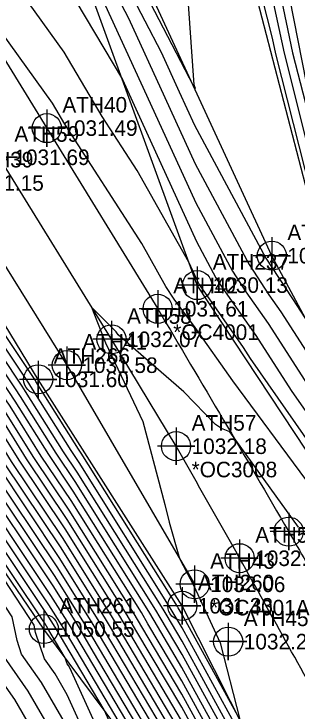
# Model space of a CAD drawing. Extents: x 1213164 to 1213550, y 766120 to 766870.
# Drawn here: x 1213382.8 to 1213428.3, y 766180 to 766292.1 of the extents above; entities that cross this region are included whole.
import ezdxf

# ---------------------------------------------------------------- set-up
doc = ezdxf.new("R2010")
doc.units = 0
for name, color, linetype in [('Default', 7, 'Continuous'), ('Exist DTM Breakline', 7, 'Continuous'), ('Exist DTM Breakline Cogo Elevation', 7, 'Continuous'), ('Exist DTM Breakline Cogo Number', 7, 'Continuous'), ('Exist DTM Breakline Cogo Point CELL', 7, 'Continuous'), ('Exist DTM Crownline', 7, 'Continuous'), ('Exist DTM Crownline Cogo Comment', 7, 'Continuous'), ('Exist DTM Crownline Cogo Elevation', 7, 'Continuous'), ('Exist DTM Crownline Cogo Number', 7, 'Continuous'), ('Exist DTM Crownline Cogo Point CELL', 7, 'Continuous'), ('Exist DTM Regular Point Cogo Comment', 7, 'Continuous'), ('Exist DTM Regular Point Cogo Elevation', 7, 'Continuous'), ('Exist DTM Regular Point Cogo Number', 7, 'Continuous'), ('Exist Hydro Stream or Body of Water', 7, 'Continuous'), ('Exist Roads EOP', 7, 'Continuous'), ('Exist Roads EOP Cogo Point CELL', 7, 'Continuous')]:
    doc.layers.add(name, color=color, linetype=linetype)

msp = doc.modelspace()

# ---------------------------------------------------------------- linework, layer by layer
at = {"layer": 'Default'}
for points in [[(1213425.78, 766168.77), (1213421.23, 766170.35), (1213409.8, 766191.25), (1213407.24, 766195.57), (1213406.74, 766196.41), (1213392.93, 766218.45), (1213390.76, 766221.69), (1213384.66, 766231.42), (1213384.09, 766232.28), (1213370.2, 766253.11), (1213367.37, 766257.44), (1213361.68, 766265.98), (1213357.81, 766271.9), (1213346.18, 766291.12), (1213344.45, 766293.74), (1213344.38, 766293.85), (1213332.56, 766311.61), (1213326.86, 766318.42), (1213322.03, 766325.64), (1213318.4, 766329.89), (1213314.05, 766335.72), (1213304.75, 766347.47), (1213303.88, 766348.56), (1213294.86, 766355.65)], [(1213427.02, 766169.17), (1213422.12, 766170.87), (1213409.81, 766193.38), (1213408.21, 766196.08), (1213407.9, 766196.6), (1213393.25, 766219.97), (1213391.95, 766221.91), (1213385.49, 766232.22), (1213385.15, 766232.72), (1213370.45, 766254.79), (1213368.43, 766257.88), (1213362.35, 766267), (1213359.46, 766271.43), (1213346.86, 766292.25), (1213345.54, 766294.24), (1213345.47, 766294.36), (1213332.57, 766313.73), (1213328.14, 766319.03), (1213322.73, 766327.12), (1213319.88, 766330.46), (1213316.46, 766335.04), (1213305.27, 766349.17), (1213304.23, 766350.49), (1213296.83, 766356.3)], [(1213424.54, 766168.36), (1213420.34, 766169.83), (1213409.79, 766189.12), (1213406.27, 766195.06), (1213405.59, 766196.21), (1213392.6, 766216.92), (1213389.56, 766221.46), (1213383.82, 766230.62), (1213383.02, 766231.83), (1213369.96, 766251.43), (1213366.3, 766257.01), (1213361.02, 766264.95), (1213356.16, 766272.38), (1213345.5, 766290), (1213343.35, 766293.24), (1213343.29, 766293.34), (1213332.54, 766309.48), (1213325.58, 766317.82), (1213321.33, 766324.16), (1213316.92, 766329.32), (1213311.63, 766336.4), (1213304.22, 766345.77), (1213303.53, 766346.64), (1213292.88, 766355.01)], [(1213422.06, 766167.56), (1213418.56, 766168.78), (1213409.76, 766184.86), (1213404.32, 766194.05), (1213403.27, 766195.83), (1213391.96, 766213.87), (1213387.17, 766221.02), (1213382.16, 766229.02), (1213380.88, 766230.94), (1213369.46, 766248.07), (1213364.18, 766256.14), (1213359.68, 766262.9), (1213352.86, 766273.33), (1213344.14, 766287.74), (1213341.16, 766292.24), (1213341.11, 766292.32), (1213332.51, 766305.24), (1213323.02, 766316.6), (1213319.94, 766321.2), (1213313.97, 766328.18), (1213306.81, 766337.76), (1213303.18, 766342.36), (1213302.84, 766342.79), (1213288.93, 766353.71)], [(1213423.3, 766167.96), (1213419.45, 766169.3), (1213409.77, 766186.99), (1213405.3, 766194.56), (1213404.43, 766196.02), (1213392.28, 766215.39), (1213388.37, 766221.24), (1213382.99, 766229.82), (1213381.95, 766231.39), (1213369.71, 766249.75), (1213365.24, 766256.58), (1213360.35, 766263.93), (1213354.51, 766272.85), (1213344.82, 766288.87), (1213342.26, 766292.74), (1213342.2, 766292.83), (1213332.53, 766307.36), (1213324.3, 766317.21), (1213320.64, 766322.68), (1213315.45, 766328.75), (1213309.22, 766337.08), (1213303.7, 766344.06), (1213303.19, 766344.71), (1213290.91, 766354.36)], [(1213419.58, 766166.76), (1213416.78, 766167.74), (1213409.74, 766180.61), (1213402.38, 766193.03), (1213400.96, 766195.44), (1213391.31, 766210.82), (1213384.78, 766220.58), (1213380.5, 766227.42), (1213378.74, 766230.05), (1213368.97, 766244.72), (1213362.06, 766255.27), (1213358.34, 766260.85), (1213349.57, 766274.28), (1213342.78, 766285.49), (1213338.97, 766291.24), (1213338.94, 766291.3), (1213332.48, 766300.99), (1213320.46, 766315.38), (1213318.55, 766318.23), (1213311.02, 766327.04), (1213302.39, 766338.6), (1213302.07, 766338.95), (1213301.81, 766339.2), (1213284.98, 766352.42)], [(1213420.82, 766167.16), (1213417.67, 766168.26), (1213409.75, 766182.74), (1213403.35, 766193.54), (1213402.12, 766195.63), (1213391.64, 766212.34), (1213385.98, 766220.8), (1213381.33, 766228.22), (1213379.81, 766230.49), (1213369.21, 766246.39), (1213363.12, 766255.71), (1213359.01, 766261.88), (1213351.22, 766273.8), (1213343.46, 766286.61), (1213340.07, 766291.74), (1213340.02, 766291.81), (1213332.5, 766303.12), (1213321.74, 766315.99), (1213319.25, 766319.71), (1213312.5, 766327.61), (1213304.4, 766338.44), (1213302.65, 766340.66), (1213302.49, 766340.86), (1213286.96, 766353.07)], [(1213410.14, 766303.65), (1213406.71, 766314.59), (1213392.41, 766329.73), (1213391.36, 766332.12), (1213385.67, 766331.97), (1213377.74, 766344.17), (1213376.85, 766345.21), (1213377.45, 766344.02), (1213377.59, 766343.78), (1213386.05, 766328.27), (1213386.98, 766326.67), (1213400.49, 766302.03), (1213411.64, 766280.51), (1213411.65, 766280.47), (1213411.66, 766280.44), (1213411.77, 766280.25), (1213411.98, 766280.11), (1213411.81, 766280.54), (1213411.74, 766280.72), (1213410.14, 766303.65)], [(1213418.34, 766166.36), (1213415.89, 766167.21), (1213409.72, 766178.48), (1213401.41, 766192.53), (1213399.8, 766195.24), (1213390.99, 766209.29), (1213383.59, 766220.36), (1213379.66, 766226.62), (1213377.67, 766229.6), (1213368.72, 766243.04), (1213360.99, 766254.84), (1213357.67, 766259.83), (1213347.92, 766274.75), (1213342.1, 766284.36), (1213337.88, 766290.74), (1213337.85, 766290.79), (1213332.47, 766298.87), (1213319.18, 766314.77), (1213317.85, 766316.75), (1213309.55, 766326.47), (1213305.45, 766331.96), (1213300.66, 766337.25), (1213296.87, 766340.88)], [(1213415.86, 766165.56), (1213414.11, 766166.17), (1213409.7, 766174.22), (1213399.47, 766191.51), (1213397.49, 766194.86), (1213390.35, 766206.24), (1213381.2, 766219.91), (1213378, 766225.02), (1213375.53, 766228.71), (1213368.22, 766239.68), (1213358.87, 766253.97), (1213356.33, 766257.78), (1213344.62, 766275.7), (1213340.74, 766282.1), (1213335.69, 766289.74), (1213335.67, 766289.77), (1213332.44, 766294.62), (1213316.62, 766313.55), (1213316.46, 766313.79), (1213314.67, 766315.89), (1213308.63, 766322.21), (1213307.01, 766323.62), (1213305.35, 766325.55), (1213297.86, 766333.83)], [(1213412.14, 766164.36), (1213411.43, 766164.6), (1213409.66, 766167.84), (1213396.55, 766189.99), (1213394.01, 766194.27), (1213389.38, 766201.66), (1213377.62, 766219.25), (1213375.5, 766222.62), (1213372.32, 766227.38), (1213367.48, 766234.65), (1213355.68, 766252.67), (1213354.33, 766254.71), (1213339.67, 766277.13), (1213338.7, 766278.72), (1213332.4, 766288.24), (1213332.4, 766288.24), (1213332.39, 766288.26), (1213332.33, 766288.33), (1213318.13, 766301.73), (1213313.49, 766307.46), (1213311.09, 766310.59), (1213309.78, 766311.96), (1213303.72, 766317.22), (1213297.53, 766324.43)], [(1213420.06, 766304.95), (1213424.27, 766288.24), (1213424.81, 766285.7), (1213431.4, 766259.7), (1213432.04, 766256.61), (1213432.14, 766256.42), (1213434.49, 766252.57), (1213436.46, 766249.05), (1213449.69, 766226.99), (1213451.6, 766226.92), (1213452.21, 766226.91), (1213473.09, 766226.2), (1213482.19, 766226.05), (1213483.85, 766226.26), (1213496.25, 766220.26), (1213501.96, 766221.57), (1213508.68, 766214.24)], [(1213398.54, 766301.17), (1213406.41, 766285.96), (1213409.33, 766279.57), (1213411.77, 766274.22), (1213423.26, 766252.86), (1213427.41, 766246.45), (1213427.64, 766246.13), (1213430.09, 766242.32)], [(1213398.3, 766167.27), (1213391.31, 766182.64), (1213389.38, 766185.97), (1213387.68, 766188.38), (1213386.25, 766192.63), (1213386.01, 766193.81), (1213370.64, 766217.27), (1213370.35, 766217.73), (1213370.21, 766218.05), (1213365.87, 766224.63), (1213365.64, 766224.88), (1213351.29, 766243.46), (1213348.01, 766247.45), (1213344.74, 766250.46), (1213339.51, 766256.88), (1213332.18, 766264.77), (1213330, 766266.59), (1213326.14, 766270), (1213320, 766275.82), (1213315.81, 766280), (1213310, 766288.06), (1213308.8, 766290), (1213300, 766299.98)], [(1213396.59, 766300.3), (1213401.19, 766291.42), (1213407.01, 766278.66), (1213411.88, 766267.99), (1213420.58, 766251.81), (1213423.73, 766246.95), (1213425.64, 766244.22), (1213440.38, 766221.3), (1213441.65, 766219.49), (1213441.73, 766219.33), (1213444.46, 766212.55), (1213448.66, 766204.27), (1213458.93, 766188.04), (1213458.45, 766186.29)], [(1213448.81, 766180.01), (1213449.77, 766183.51), (1213448.71, 766185.18), (1213442.01, 766198.4), (1213436.88, 766206.89), (1213435.93, 766208.37), (1213435.34, 766209.2), (1213434.63, 766210.13), (1213433.49, 766211.95), (1213429.68, 766217.27), (1213417.95, 766233.12), (1213411.88, 766241.68), (1213408.5, 766246.27), (1213407.19, 766248.31), (1213403.31, 766255.2), (1213390.98, 766274.37), (1213388.98, 766277.75), (1213373.78, 766298.94)], [(1213451.22, 766181.58), (1213452.06, 766184.64), (1213448.7, 766189.95), (1213438.1, 766210.84), (1213437.62, 766212.04), (1213436.61, 766214.01), (1213420.81, 766236.7), (1213419.66, 766238.5), (1213412.69, 766248.45), (1213412.56, 766248.64), (1213412.21, 766249.3), (1213410.88, 766252.21), (1213402.59, 766266.93), (1213396.98, 766275.64), (1213390.85, 766285.97), (1213381.51, 766299)], [(1213424.74, 766299.28), (1213427.56, 766285.88), (1213429.63, 766277.75), (1213434, 766256.55), (1213434.74, 766255.23), (1213435.33, 766254.27), (1213445.35, 766236.36), (1213450.26, 766228.16), (1213450.97, 766228.14), (1213452.49, 766228.12), (1213460.35, 766227.85), (1213482.44, 766227.49), (1213486.49, 766228.01), (1213491.53, 766225.56), (1213516.94, 766231.38), (1213519.02, 766229.11), (1213527.88, 766208.79)], [(1213406.02, 766158.46), (1213404.75, 766161.75), (1213403.99, 766165.4), (1213397.26, 766180.19), (1213392.67, 766187.96), (1213389.39, 766193.5), (1213388.09, 766195.56), (1213372.84, 766218.36), (1213372.18, 766219.42), (1213368.04, 766225.6), (1213366.49, 766227.93), (1213355.2, 766245.18), (1213351.86, 766249.5), (1213351.15, 766250.37), (1213350.44, 766251.02), (1213338.92, 766265.16), (1213334.51, 766269.9), (1213332.06, 766271.95), (1213324.14, 766279.45), (1213322.27, 766281.51), (1213320, 766284.17), (1213315.66, 766290), (1213310, 766297.41)], [(1213410.9, 766163.96), (1213410.54, 766164.08), (1213409.65, 766165.71), (1213395.58, 766189.48), (1213392.86, 766194.08), (1213389.06, 766200.14), (1213376.42, 766219.03), (1213374.67, 766221.82), (1213371.25, 766226.93), (1213367.23, 766232.97), (1213354.62, 766252.24), (1213353.66, 766253.68), (1213338.05, 766277.55), (1213338.03, 766277.58), (1213338.02, 766277.59), (1213338.02, 766277.59), (1213338.01, 766277.6), (1213329.88, 766286.57), (1213327.91, 766288.87), (1213318.81, 766297.46)], [(1213413.38, 766164.76), (1213412.32, 766165.13), (1213409.68, 766169.97), (1213397.52, 766190.49), (1213395.17, 766194.47), (1213389.7, 766203.19), (1213378.81, 766219.47), (1213376.34, 766223.42), (1213373.39, 766227.82), (1213367.73, 766236.32), (1213356.74, 766253.1), (1213355, 766255.73), (1213341.32, 766276.65), (1213339.38, 766279.85), (1213333.5, 766288.74), (1213333.49, 766288.75), (1213332.41, 766290.38), (1213326.45, 766297.51)], [(1213390.86, 766178.31), (1213387.23, 766184.59), (1213384.01, 766189.16), (1213383.27, 766191.37), (1213382.47, 766195.18), (1213370.5, 766213.46), (1213368.64, 766216.45), (1213367.71, 766218.53), (1213364.43, 766223.5), (1213362.13, 766226.03), (1213351, 766240.43), (1213346.44, 766245.99), (1213341.89, 766250.18), (1213339.8, 766252.74), (1213331.01, 766262.21), (1213330, 766263.05), (1213322.14, 766270), (1213320, 766272.03), (1213312.01, 766280), (1213310, 766282.79), (1213305.54, 766290), (1213300, 766296.28)], [(1213417.1, 766165.96), (1213415, 766166.69), (1213409.71, 766176.35), (1213400.44, 766192.02), (1213398.64, 766195.05), (1213390.67, 766207.77), (1213382.39, 766220.14), (1213378.83, 766225.82), (1213376.6, 766229.16), (1213368.47, 766241.36), (1213359.93, 766254.41), (1213357, 766258.81), (1213346.27, 766275.23), (1213341.42, 766283.23), (1213336.78, 766290.24), (1213336.76, 766290.28), (1213332.45, 766296.75)], [(1213395.96, 766296.87), (1213404.69, 766277.75), (1213411.99, 766261.76), (1213417.91, 766250.75), (1213420.05, 766247.45), (1213423.65, 766242.32), (1213433.86, 766226.44), (1213439.97, 766217.66), (1213440.36, 766216.9), (1213442.34, 766211.98), (1213448.67, 766199.5), (1213456.64, 766186.9), (1213456.04, 766184.72)], [(1213392.73, 766294.19), (1213400.2, 766281.6), (1213402.37, 766276.84), (1213412.1, 766255.53), (1213415.23, 766249.7), (1213416.37, 766247.95), (1213421.65, 766240.41), (1213427.34, 766231.57), (1213438.29, 766215.83), (1213438.99, 766214.47), (1213440.22, 766211.41), (1213448.68, 766194.73), (1213454.35, 766185.77), (1213453.63, 766183.15)], [(1213401.15, 766166.34), (1213391.76, 766186.97), (1213391.54, 766187.34), (1213391.35, 766187.61), (1213391.03, 766188.57), (1213388.23, 766193.3), (1213387.77, 766194.04), (1213371.64, 766218.14), (1213371.34, 766218.62), (1213366.97, 766225.15), (1213366.24, 766226.25), (1213360.92, 766234.39), (1213351.57, 766246.48), (1213349.58, 766248.91), (1213347.59, 766250.74), (1213339.21, 766261.02), (1213333.35, 766267.33), (1213330.07, 766270.07), (1213327.46, 766272.54), (1213320, 766279.61), (1213319.61, 766280), (1213318.6, 766281.4), (1213312.19, 766290), (1213310, 766292.87)], [(1213407.84, 766161.03), (1213407.21, 766162.66), (1213406.84, 766164.47), (1213403.5, 766171.81), (1213393.64, 766188.46), (1213390.54, 766193.69), (1213388.41, 766197.09), (1213374.03, 766218.59), (1213373.01, 766220.22), (1213369.11, 766226.04), (1213366.74, 766229.61), (1213352.5, 766251.37), (1213352.32, 766251.63), (1213349.48, 766255.97), (1213338.62, 766269.3), (1213335.68, 766272.46), (1213334.04, 766273.83), (1213328.77, 766278.83), (1213324.81, 766283.2), (1213320, 766288.82), (1213319.12, 766290), (1213316.29, 766293.71)], [(1213409.66, 766163.56), (1213409.65, 766163.56), (1213409.64, 766163.58), (1213394.61, 766188.97), (1213391.7, 766193.88), (1213388.73, 766198.61), (1213375.23, 766218.81), (1213373.84, 766221.02), (1213370.18, 766226.49), (1213366.98, 766231.29), (1213353.56, 766251.8), (1213352.99, 766252.66), (1213343.77, 766266.76), (1213338.32, 766273.44), (1213336.85, 766275.02), (1213336.03, 766275.71), (1213333.39, 766278.22), (1213327.35, 766284.88), (1213323.38, 766289.52), (1213319.49, 766293.19)], [(1213424.51, 766293.76), (1213426.19, 766285.79), (1213430.51, 766268.72), (1213433.02, 766256.58), (1213433.44, 766255.82), (1213434.91, 766253.42), (1213440.91, 766242.7), (1213449.98, 766227.57), (1213451.29, 766227.53), (1213452.35, 766227.51), (1213466.72, 766227.02), (1213482.31, 766226.77), (1213485.17, 766227.14), (1213493.89, 766222.91), (1213509.45, 766226.47), (1213524.7, 766209.84), (1213525.67, 766207.61)], [(1213390.41, 766173.98), (1213385.07, 766183.22), (1213380.34, 766189.93), (1213380.28, 766190.12), (1213378.93, 766196.54), (1213370.36, 766209.64), (1213366.93, 766215.17), (1213365.2, 766219.01), (1213362.99, 766222.36), (1213358.62, 766227.18), (1213350.71, 766237.41), (1213344.87, 766244.53), (1213340, 766249.02), (1213338.96, 766250), (1213330, 766259.54), (1213329.52, 766260), (1213320, 766268.56), (1213318.32, 766270), (1213310, 766278.29), (1213308.79, 766279.73), (1213308.65, 766280), (1213305.97, 766284.03), (1213302.28, 766290), (1213300, 766292.58)], [(1213414.62, 766165.16), (1213413.22, 766165.65), (1213409.69, 766172.1), (1213398.5, 766191), (1213396.33, 766194.66), (1213390.02, 766204.72), (1213380.01, 766219.69), (1213377.17, 766224.22), (1213374.46, 766228.27), (1213367.97, 766238), (1213357.81, 766253.54), (1213355.67, 766256.76), (1213342.97, 766276.18), (1213340.06, 766280.98), (1213334.59, 766289.24), (1213334.58, 766289.26), (1213332.42, 766292.5)], [(1213428.5, 766209.6), (1213417.49, 766224.93), (1213416.15, 766225.43), (1213415.16, 766226.09), (1213410.07, 766231.37), (1213399.53, 766240.51), (1213399.2, 766240.98), (1213395.25, 766244.97), (1213397.28, 766239.75), (1213397.47, 766239.22), (1213403.47, 766226.58), (1213407.05, 766213.24), (1213407.74, 766210.4), (1213409.38, 766204.55), (1213411.66, 766200.12), (1213415.93, 766191), (1213419.06, 766178.63), (1213409.82, 766195.51), (1213409.18, 766196.59), (1213409.06, 766196.8), (1213393.57, 766221.5), (1213393.15, 766222.13), (1213386.32, 766233.02), (1213386.22, 766233.17), (1213370.7, 766256.46)], [(1213389.43, 766170.57), (1213382.91, 766181.85), (1213380, 766185.98)]]:
    msp.add_lwpolyline(points, dxfattribs=at)
at = {"layer": 'Exist DTM Breakline'}
for points in [[(1213525.39, 766207.47), (1213482.01, 766225.05), (1213449.3, 766226.19), (1213431.7, 766256.62), (1213419.18, 766304.88), (1213413.48, 766348.82), (1213382.31, 766373.43), (1213372.71, 766395.69), (1213369.18, 766434.58), (1213366.95, 766449.61), (1213359.43, 766466.81), (1213345.1, 766468.72)], [(1213422.78, 766171.25), (1213409.83, 766196.93), (1213386.66, 766233.35), (1213364.33, 766270.03), (1213348.91, 766295.97), (1213348.91, 766295.97), (1213325.28, 766332.54), (1213305.81, 766359.24), (1213281.25, 766381.47), (1213256.99, 766395.59), (1213227.81, 766408.56), (1213197.43, 766416.07)], [(1213448.72, 766182.98), (1213435.67, 766212.97), (1213412.22, 766248.51), (1213393.85, 766299.08), (1213370.87, 766342.59), (1213356.52, 766367.11), (1213355.51, 766406.8)], [(1213468.09, 766192.57), (1213448.63, 766213.66), (1213442.08, 766219.96), (1213424.22, 766253.24), (1213401.52, 766302.49), (1213377.56, 766344.05), (1213361.4, 766370.67), (1213365.74, 766393.84)], [(1213409.64, 766163.55), (1213387.59, 766193.2), (1213366.02, 766224.76), (1213332.39, 766288.23), (1213308.21, 766325.96), (1213302.17, 766339.08)]]:
    msp.add_lwpolyline(points, dxfattribs=at)
at = {"layer": 'Exist DTM Breakline Cogo Point CELL'}
for points in [[(1213424.22, 766256.24), (1213424.22, 766250.24), (1213424.22, 766253.24), (1213427.22, 766253.24), (1213421.22, 766253.24)], [(1213412.22, 766251.51), (1213412.22, 766245.51), (1213412.22, 766248.51), (1213415.22, 766248.51), (1213409.22, 766248.51)], [(1213386.66, 766236.35), (1213386.66, 766230.35), (1213386.66, 766233.35), (1213389.66, 766233.35), (1213383.66, 766233.35)], [(1213409.83, 766199.93), (1213409.83, 766193.93), (1213409.83, 766196.93), (1213412.83, 766196.93), (1213406.83, 766196.93)], [(1213387.59, 766196.2), (1213387.59, 766190.2), (1213387.59, 766193.2), (1213390.59, 766193.2), (1213384.59, 766193.2)]]:
    msp.add_lwpolyline(points, dxfattribs=at)
for centre in [(1213424.22, 766253.24), (1213412.22, 766248.51), (1213386.66, 766233.35), (1213409.83, 766196.93), (1213387.59, 766193.2)]:
    msp.add_circle(centre, 2.34, dxfattribs=at)
at = {"layer": 'Exist DTM Crownline'}
msp.add_lwpolyline([(1213408.83, 766222.6), (1213398.45, 766239.79), (1213380.35, 766269.07), (1213364.82, 766294.53)], dxfattribs=at)
msp.add_spline([(1213434.71, 766176.25), (1213419.05, 766204.58), (1213408.83, 766222.6)], degree=3, dxfattribs=at)
at = {"layer": 'Exist DTM Crownline Cogo Point CELL'}
for points in [[(1213380.35, 766272.07), (1213380.35, 766266.07), (1213380.35, 766269.07), (1213383.35, 766269.07), (1213377.35, 766269.07)], [(1213398.45, 766242.79), (1213398.45, 766236.79), (1213398.45, 766239.79), (1213401.45, 766239.79), (1213395.45, 766239.79)], [(1213408.83, 766225.6), (1213408.83, 766219.6), (1213408.83, 766222.6), (1213411.83, 766222.6), (1213405.83, 766222.6)], [(1213419.05, 766207.58), (1213419.05, 766201.58), (1213419.05, 766204.58), (1213422.05, 766204.58), (1213416.05, 766204.58)]]:
    msp.add_lwpolyline(points, dxfattribs=at)
for centre in [(1213398.45, 766239.79), (1213408.83, 766222.6), (1213419.05, 766204.58)]:
    msp.add_circle(centre, 2.34, dxfattribs=at)
at = {"layer": 'Exist Hydro Stream or Body of Water'}
msp.add_lwpolyline([(1213528.18, 766208.95), (1213518.13, 766232.16), (1213482.65, 766228.64), (1213450.6, 766228.86), (1213434.62, 766256.54), (1213425, 766305.33), (1213420.53, 766356.32), (1213385.1, 766376.62), (1213376.32, 766397.22), (1213374.29, 766436.33), (1213371.57, 766451.85), (1213360.53, 766468.46), (1213342.81, 766469.47)], dxfattribs=at)
at = {"layer": 'Exist Roads EOP'}
for p, q in [((1213372.58, 766298.93), (1213388.06, 766273.76)), ((1213388.06, 766273.76), (1213405.88, 766244.7))]:
    msp.add_line(p, q, dxfattribs=at)
msp.add_lwpolyline([(1213357.31, 766290.43), (1213372.99, 766264.94), (1213391.28, 766235.63), (1213411.81, 766200.39)], dxfattribs=at)
msp.add_spline([(1213405.88, 766244.7), (1213426.93, 766208.86), (1213432.41, 766199.22), (1213442.58, 766180.07)], degree=3, dxfattribs=at)
at = {"layer": 'Exist Roads EOP Cogo Point CELL'}
for points in [[(1213388.06, 766276.76), (1213388.06, 766270.76), (1213388.06, 766273.76), (1213391.06, 766273.76), (1213385.06, 766273.76)], [(1213405.88, 766247.7), (1213405.88, 766241.7), (1213405.88, 766244.7), (1213408.88, 766244.7), (1213402.88, 766244.7)], [(1213391.28, 766238.63), (1213391.28, 766232.63), (1213391.28, 766235.63), (1213394.28, 766235.63), (1213388.28, 766235.63)], [(1213426.93, 766211.86), (1213426.93, 766205.86), (1213426.93, 766208.86), (1213429.93, 766208.86), (1213423.93, 766208.86)], [(1213411.81, 766203.39), (1213411.81, 766197.39), (1213411.81, 766200.39), (1213414.81, 766200.39), (1213408.81, 766200.39)], [(1213417.21, 766194.17), (1213417.21, 766188.17), (1213417.21, 766191.17), (1213420.21, 766191.17), (1213414.21, 766191.17)]]:
    msp.add_lwpolyline(points, dxfattribs=at)
for centre in [(1213388.06, 766273.76), (1213405.88, 766244.7), (1213391.28, 766235.63), (1213426.93, 766208.86), (1213411.81, 766200.39), (1213417.21, 766191.17)]:
    msp.add_circle(centre, 2.34, dxfattribs=at)

# ---------------------------------------------------------------- texts
at = {"layer": 'Exist DTM Breakline Cogo Elevation'}
for s, p in [('1025.64', (1213426.72, 766251.99)), ('1030.13', (1213414.72, 766247.26)), ('1031.60', (1213389.16, 766232.1)), ('1031.33', (1213412.33, 766195.68)), ('1050.55', (1213390.09, 766191.95))]:
    msp.add_text(s, height=2.5, dxfattribs=at).set_placement(p)
at = {"layer": 'Exist DTM Breakline Cogo Number'}
for s, p in [('ATH238', (1213426.72, 766255.74)), ('ATH237', (1213414.72, 766251.01)), ('ATH266', (1213389.16, 766235.85)), ('ATH260', (1213412.33, 766199.43)), ('ATH261', (1213390.09, 766195.7))]:
    msp.add_text(s, height=2.5, dxfattribs=at).set_placement(p)
at = {"layer": 'Exist DTM Crownline Cogo Comment'}
msp.add_text('*OC3008', height=2.5, dxfattribs=at).set_placement((1213411.33, 766217.6))
at = {"layer": 'Exist DTM Crownline Cogo Elevation'}
for s, p in [('1031.69', (1213382.85, 766267.82)), ('1032.07', (1213400.95, 766238.54)), ('1032.18', (1213411.33, 766221.35)), ('1032.45', (1213421.55, 766203.33))]:
    msp.add_text(s, height=2.5, dxfattribs=at).set_placement(p)
at = {"layer": 'Exist DTM Crownline Cogo Number'}
for s, p in [('ATH59', (1213382.85, 766271.57)), ('ATH58', (1213400.95, 766242.29)), ('ATH57', (1213411.33, 766225.1)), ('ATH56', (1213421.55, 766207.08))]:
    msp.add_text(s, height=2.5, dxfattribs=at).set_placement(p)
at = {"layer": 'Exist DTM Regular Point Cogo Comment'}
for s, p in [('*OC4001', (1213408.38, 766239.7)), ('*OC4001A', (1213414.31, 766195.39))]:
    msp.add_text(s, height=2.5, dxfattribs=at).set_placement(p)
at = {"layer": 'Exist DTM Regular Point Cogo Elevation'}
for s, p in [('1031.49', (1213390.56, 766272.51)), ('1031.15', (1213375.49, 766263.69)), ('1031.61', (1213408.38, 766243.45)), ('1031.58', (1213393.78, 766234.38)), ('1032.06', (1213414.31, 766199.14)), ('1032.25', (1213419.71, 766189.92))]:
    msp.add_text(s, height=2.5, dxfattribs=at).set_placement(p)
at = {"layer": 'Exist DTM Regular Point Cogo Number'}
for s, p in [('ATH40', (1213390.56, 766276.26)), ('ATH39', (1213375.49, 766267.44)), ('ATH42', (1213408.38, 766247.2)), ('ATH41', (1213393.78, 766238.13)), ('ATH43', (1213414.31, 766202.89)), ('ATH45', (1213419.71, 766193.67))]:
    msp.add_text(s, height=2.5, dxfattribs=at).set_placement(p)

doc.saveas('drawing.dxf')
